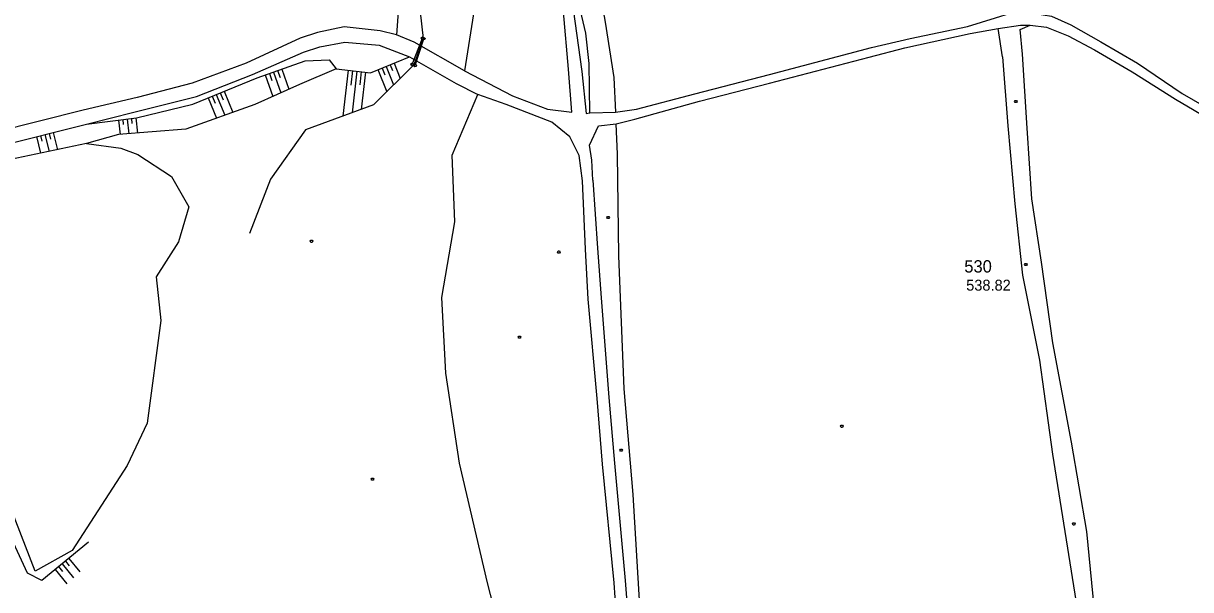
# Model space of a CAD drawing. Extents: x -664960 to -662754, y -993849 to -991145.
# Drawn here: x -663773.7 to -663452.1, y -992215.3 to -992059.4 of the extents above; entities that cross this region are included whole.
import ezdxf

# ---------------------------------------------------------------- set-up
doc = ezdxf.new("R2010")
doc.units = 0
for name, color, linetype in [('Vrstva 1', 7, 'Continuous'), ('Vrstva 13', 7, 'Continuous'), ('Vrstva 24', 7, 'Continuous'), ('Vrstva 27', 7, 'Continuous'), ('Vrstva 28', 7, 'Continuous'), ('Vrstva 33', 7, 'Continuous'), ('Vrstva 63', 7, 'Continuous'), ('Vrstva 8', 7, 'Continuous')]:
    doc.layers.add(name, color=color, linetype=linetype)

msp = doc.modelspace()

# ---------------------------------------------------------------- linework, layer by layer
at = {"layer": 'Vrstva 13'}
for points in [[(-663500.081, -992080.583), (-663499.901, -992080.883), (-663500.081, -992081.183), (-663500.441, -992081.183), (-663500.621, -992080.883), (-663500.441, -992080.583), (-663500.081, -992080.583)], [(-663612.408, -992112.523), (-663612.228, -992112.823), (-663612.408, -992113.123), (-663612.768, -992113.123), (-663612.948, -992112.823), (-663612.768, -992112.523), (-663612.408, -992112.523)], [(-663694.093, -992119.079), (-663693.913, -992119.379), (-663694.093, -992119.679), (-663694.453, -992119.679), (-663694.633, -992119.379), (-663694.453, -992119.079), (-663694.093, -992119.079)], [(-663636.781, -992145.489), (-663636.601, -992145.789), (-663636.781, -992146.089), (-663637.141, -992146.089), (-663637.321, -992145.789), (-663637.141, -992145.489), (-663636.781, -992145.489)], [(-663548.037, -992170.022), (-663547.857, -992170.322), (-663548.037, -992170.622), (-663548.397, -992170.622), (-663548.577, -992170.322), (-663548.397, -992170.022), (-663548.037, -992170.022)], [(-663608.823, -992176.582), (-663608.643, -992176.882), (-663608.823, -992177.182), (-663609.183, -992177.182), (-663609.363, -992176.882), (-663609.183, -992176.582), (-663608.823, -992176.582)], [(-663677.291, -992184.592), (-663677.111, -992184.892), (-663677.291, -992185.192), (-663677.651, -992185.192), (-663677.831, -992184.892), (-663677.651, -992184.592), (-663677.291, -992184.592)], [(-663484.097, -992196.909), (-663483.917, -992197.209), (-663484.097, -992197.509), (-663484.457, -992197.509), (-663484.637, -992197.209), (-663484.457, -992196.909), (-663484.097, -992196.909)]]:
    msp.add_lwpolyline(points, dxfattribs=at)
at = {"layer": 'Vrstva 24'}
for p, q in [((-663666.555, -992070.68), (-663663.701, -992063.457)), ((-663665.708, -992070.984), (-663663.325, -992063.591))]:
    msp.add_line(p, q, dxfattribs=at)
for points in [[(-663663.979, -992063.669), (-663664.036, -992063.324), (-663663.759, -992063.111), (-663663.424, -992063.244), (-663663.367, -992063.589), (-663663.644, -992063.802), (-663663.979, -992063.669)], [(-663663.555, -992063.328), (-663663.214, -992063.249), (-663662.984, -992063.512), (-663663.095, -992063.855), (-663663.436, -992063.934), (-663663.666, -992063.67), (-663663.555, -992063.328)], [(-663666.278, -992070.467), (-663666.221, -992070.812), (-663666.498, -992071.025), (-663666.833, -992070.893), (-663666.89, -992070.548), (-663666.613, -992070.335), (-663666.278, -992070.467)], [(-663665.938, -992070.72), (-663665.597, -992070.641), (-663665.367, -992070.905), (-663665.478, -992071.247), (-663665.819, -992071.326), (-663666.049, -992071.063), (-663665.938, -992070.72)]]:
    msp.add_lwpolyline(points, dxfattribs=at)
at = {"layer": 'Vrstva 27'}
for p, q in [((-663617.662, -992084.005), (-663610.509, -992083.791)), ((-663610.371, -992087.031), (-663610.371, -992087.031)), ((-663619.645, -992102.742), (-663620.564, -992095.802))]:
    msp.add_line(p, q, dxfattribs=at)
for points in [[(-663652.149, -992072.457), (-663638.894, -992079.322), (-663629.252, -992082.973), (-663622.572, -992083.804), (-663623.507, -992071.963), (-663624.89, -992056.198), (-663630.063, -992031.166), (-663634.545, -992007.215), (-663637.859, -991989.522), (-663641.354, -991966.119), (-663644.017, -991941.494), (-663646.236, -991915.956), (-663649.418, -991889.892), (-663652.546, -991864.285), (-663654.41, -991840.241), (-663656.328, -991820.074), (-663658.665, -991801.934), (-663661.329, -991790.355), (-663663.806, -991781.544)], [(-663660.976, -991780.777), (-663658.558, -991789.771), (-663655.323, -991801.705), (-663653.202, -991819.768), (-663651.587, -991840.172), (-663649.787, -991863.83), (-663646.312, -991889.394), (-663643.411, -991916.091), (-663641.041, -991940.893), (-663638.598, -991965.955), (-663635.066, -991988.904), (-663631.676, -992006.332), (-663627.229, -992030.816), (-663622.18, -992055.438), (-663619.865, -992072.617), (-663618.624, -992084.162), (-663617.662, -992084.005)], [(-663610.509, -992083.791), (-663604.798, -992083.037), (-663588.741, -992078.775), (-663568.158, -992073.414), (-663540.034, -992066.054), (-663529.382, -992063.582), (-663513.636, -992060.192), (-663505.874, -992057.816)], [(-663505.874, -992057.816), (-663501.741, -992056.574), (-663497.34, -992056.267), (-663490.468, -992057.436), (-663485.138, -992059.768), (-663476.877, -992064.439), (-663466.765, -992070.371), (-663454.437, -992078.707), (-663436.313, -992089.167), (-663416.04, -992100.061), (-663402.598, -992105.966), (-663390.777, -992109.645), (-663381.893, -992111.637), (-663376.011, -992112.573), (-663374.014, -992111.876)], [(-663652.149, -992072.457), (-663666.048, -992064.522), (-663670.915, -992062.515), (-663675.397, -992061.433), (-663685.315, -992060.33), (-663692.602, -992061.892), (-663697.435, -992063.44), (-663712.242, -992070.367), (-663727.163, -992075.883), (-663742.301, -992079.812), (-663757.17, -992083.235), (-663781.317, -992089.372), (-663789.254, -992091.031), (-663815.063, -992094.6), (-663832.035, -992101.429), (-663841.787, -992109.827), (-663853.332, -992124.858), (-663861.753, -992138.392), (-663865.565, -992146.055), (-663870.358, -992158.296), (-663873.442, -992172.032), (-663874.279, -992185.452), (-663873.423, -992201.852), (-663871.565, -992214.969)], [(-663610.371, -992087.031), (-663605.274, -992085.712), (-663587.403, -992080.826), (-663568.125, -992075.859), (-663540.707, -992068.649), (-663530.863, -992066.12), (-663512.89, -992062.21), (-663505.164, -992060.778)], [(-663505.164, -992060.778), (-663499.035, -992059.84), (-663496.315, -992059.878), (-663491.826, -992060.396), (-663485.827, -992062.825), (-663478.629, -992066.63), (-663468.226, -992072.7), (-663456.349, -992080.226), (-663437.31, -992091.482), (-663416.912, -992102.28), (-663405.126, -992108.137), (-663391.371, -992112.531), (-663381.874, -992114.453), (-663376.408, -992115.427), (-663372.877, -992116.89), (-663369.899, -992119.472)], [(-663867.768, -992214.752), (-663869.372, -992201.64), (-663870.276, -992185.241), (-663869.416, -992173.115), (-663866.625, -992159.618), (-663862.399, -992148.688), (-663858.277, -992140.51), (-663850.111, -992126.922), (-663839.032, -992112.926), (-663829.283, -992104.516), (-663813.981, -992098.887), (-663790.431, -992094.971), (-663780.543, -992093.142), (-663756.27, -992087.113), (-663743.198, -992083.857), (-663725.949, -992079.492), (-663710.496, -992073.411), (-663696.524, -992067.259), (-663692.016, -992065.833), (-663685.143, -992064.515), (-663675.656, -992065.396), (-663667.253, -992068.6), (-663654.396, -992075.969), (-663648.46, -992078.95)], [(-663628.118, -992086.576), (-663640.641, -992081.732), (-663648.46, -992078.95)], [(-663620.564, -992095.802), (-663623.092, -992090.585), (-663628.118, -992086.576)], [(-663617.68, -992092.91), (-663615.26, -992087.61), (-663610.371, -992087.031)], [(-663616.772, -992102.525), (-663617.1, -992097.01), (-663617.68, -992092.91)], [(-663609.18, -992284), (-663609.46, -992267.9), (-663609.2, -992261.28), (-663609.26, -992237.69), (-663610.89, -992213.38), (-663614.18, -992180.71), (-663615.56, -992162.64), (-663618.05, -992135.28), (-663618.78, -992121.53), (-663619.645, -992102.742)], [(-663616.772, -992102.525), (-663615.49, -992121.31), (-663614.49, -992134.95), (-663612.38, -992162.38), (-663610.82, -992180.49), (-663607.92, -992212.78), (-663606.07, -992236.58), (-663606.22, -992261.4), (-663605.35, -992288.4)]]:
    msp.add_lwpolyline(points, dxfattribs=at)
at = {"layer": 'Vrstva 28'}
for p, q in [((-663667.952, -992025.484), (-663663.513, -992063.524)), ((-663663.513, -992063.524), (-663666.132, -992070.832))]:
    msp.add_line(p, q, dxfattribs=at)
msp.add_lwpolyline([(-663666.132, -992070.832), (-663677.21, -992081.835), (-663695.934, -992088.709), (-663705.595, -992102.302), (-663711.407, -992117.193)], dxfattribs=at)
at = {"layer": 'Vrstva 33'}
msp.add_lwpolyline([(-663625.96, -992122.04), (-663625.78, -992122.34), (-663625.96, -992122.64), (-663626.32, -992122.64), (-663626.5, -992122.34), (-663626.32, -992122.04), (-663625.96, -992122.04)], dxfattribs=at)
at = {"layer": 'Vrstva 63'}
for p, q in [((-663503.985, -992068.553), (-663505.164, -992060.778)), ((-663702.494, -992071.967), (-663700.511, -992077.529)), ((-663684.167, -992072.26), (-663685.623, -992084.923)), ((-663675.975, -992072.114), (-663673.531, -992078.181)), ((-663674.862, -992071.665), (-663674.111, -992073.529)), ((-663673.749, -992071.217), (-663671.683, -992076.345)), ((-663672.636, -992070.769), (-663672.011, -992072.32)), ((-663671.523, -992070.32), (-663669.835, -992074.51)), ((-663707.015, -992073.579), (-663704.904, -992079.502)), ((-663705.885, -992073.176), (-663705.192, -992075.118)), ((-663704.754, -992072.773), (-663702.708, -992078.515)), ((-663703.624, -992072.37), (-663702.953, -992074.252)), ((-663682.975, -992072.397), (-663683.437, -992076.414)), ((-663681.783, -992072.534), (-663683.101, -992083.997)), ((-663680.591, -992072.671), (-663681.007, -992076.289)), ((-663679.399, -992072.808), (-663680.579, -992083.071)), ((-663719.416, -992078.542), (-663718.632, -992080.456)), ((-663718.306, -992078.087), (-663715.928, -992083.888)), ((-663722.747, -992079.907), (-663720.455, -992085.5)), ((-663721.637, -992079.452), (-663720.867, -992081.332)), ((-663720.527, -992078.997), (-663718.192, -992084.694)), ((-663747.481, -992086.012), (-663746.986, -992089.968)), ((-663746.29, -992085.863), (-663746.123, -992087.198)), ((-663745.1, -992085.714), (-663744.591, -992089.776)), ((-663743.909, -992085.565), (-663743.738, -992086.935)), ((-663742.718, -992085.416), (-663742.197, -992089.583)), ((-663609.968, -992095.397), (-663610.371, -992087.031)), ((-663770.069, -992090.54), (-663768.927, -992095.137)), ((-663768.904, -992090.251), (-663768.52, -992091.796)), ((-663767.739, -992089.961), (-663766.576, -992094.646)), ((-663766.575, -992089.672), (-663766.184, -992091.247)), ((-663765.41, -992089.383), (-663764.225, -992094.154)), ((-663761.146, -992206.687), (-663758.117, -992210.394)), ((-663764.863, -992209.724), (-663761.642, -992213.665)), ((-663763.934, -992208.965), (-663762.877, -992210.258)), ((-663763.005, -992208.206), (-663759.879, -992212.03)), ((-663762.075, -992207.446), (-663761.051, -992208.7))]:
    msp.add_line(p, q, dxfattribs=at)
for points in [[(-663617.662, -992084.005), (-663617.796, -992070.405), (-663618.685, -992062.035), (-663620.6, -992054.289), (-663624.555, -992034.438), (-663627.573, -992021.077), (-663630.439, -992005.417), (-663633.594, -991988.6), (-663636.017, -991965.823), (-663639.158, -991940.551), (-663641.433, -991916.279), (-663644.548, -991888.909), (-663648.221, -991863.623), (-663649.938, -991840.103), (-663650.821, -991819.63), (-663650.995, -991810.793), (-663652.021, -991800.876), (-663653.776, -991788.518), (-663656.114, -991774.485), (-663657.935, -991762.249), (-663658.157, -991746.16), (-663659.154, -991720.205)], [(-663625.612, -991996.822), (-663623.58, -992006.69), (-663618.949, -992028.863), (-663616.597, -992040.728), (-663613.419, -992059.024), (-663611.042, -992074.3), (-663610.509, -992083.791)], [(-663687.235, -992025.666), (-663672.631, -992026.425), (-663669.875, -992048.621), (-663670.915, -992062.515)], [(-663649.704, -992056.772), (-663652.149, -992072.457)], [(-663498.448, -992067.861), (-663499.131, -992061.103), (-663496.315, -992059.878)], [(-663756.27, -992087.113), (-663742.496, -992085.388), (-663726.974, -992081.64), (-663709.26, -992074.379), (-663696.074, -992069.679), (-663689.436, -992069.427), (-663687.539, -992071.872), (-663678.076, -992072.96), (-663667.253, -992068.6)], [(-663503.985, -992068.553), (-663502.49, -992087.58), (-663500.52, -992109.05), (-663498.42, -992128.71), (-663493.79, -992152.11), (-663490.17, -992178.03), (-663483.06, -992222.86), (-663480.63, -992245.25), (-663480.32, -992267.2)], [(-663475.97, -992273.64), (-663476, -992255.14), (-663478.3, -992223.8), (-663480.74, -992199.31), (-663484.94, -992174.65), (-663490.09, -992147.35), (-663493.26, -992125.09), (-663495.9, -992107.68), (-663497.17, -992088.23), (-663498.448, -992067.861)], [(-663687.539, -992071.872), (-663697.594, -992076.22), (-663709.856, -992081.725), (-663728.917, -992088.514), (-663747.464, -992090.007), (-663756.253, -992092.487), (-663780.731, -992097.606), (-663792.314, -992099.303), (-663814.145, -992102.581), (-663827.055, -992107.734), (-663836.598, -992115.531), (-663846.58, -992127.329), (-663856.223, -992141.469), (-663859.063, -992150.47), (-663866.625, -992159.618)], [(-663633.3, -992287.85), (-663635.84, -992266.79), (-663638.48, -992251.41), (-663641.84, -992228.79), (-663645.82, -992213.4), (-663653.56, -992180.51), (-663657.32, -992155.71), (-663658.36, -992134.88), (-663654.79, -992114.04), (-663655.56, -992095.7), (-663648.46, -992078.95)], [(-663756.253, -992092.487), (-663746.828, -992093.758), (-663742.121, -992095.479), (-663732.85, -992101.523), (-663728.116, -992109.932), (-663730.943, -992119.569), (-663737.051, -992129.159), (-663735.83, -992141.172), (-663739.547, -992169.479), (-663745.097, -992181.09), (-663760.244, -992204.525), (-663770.418, -992210.225), (-663778.389, -992189.549), (-663784.771, -992179.426), (-663793.726, -992169.45), (-663808.984, -992173.8), (-663812.912, -992183.474)], [(-663481.51, -992286.47), (-663501.02, -992286.13), (-663518.86, -992285.48), (-663556.12, -992281.38), (-663564.44, -992280.33), (-663573.46, -992278.84), (-663585.77, -992276.23), (-663602.73, -992270.11), (-663602.69, -992238.93), (-663603.85, -992219.76), (-663605.7, -992189.06), (-663608.17, -992160.04), (-663609.68, -992123.43), (-663609.968, -992095.397)], [(-663755.675, -992202.216), (-663768.567, -992212.751), (-663772.484, -992210.734), (-663781.84, -992190.688), (-663786.31, -992183.558), (-663794.872, -992173.974), (-663804.64, -992174.043), (-663812.912, -992183.474)]]:
    msp.add_lwpolyline(points, dxfattribs=at)
at = {"layer": 'Vrstva 8'}
msp.add_lwpolyline([(-663497.38, -992125.47), (-663497.2, -992125.77), (-663497.38, -992126.07), (-663497.74, -992126.07), (-663497.92, -992125.77), (-663497.74, -992125.47), (-663497.38, -992125.47)], dxfattribs=at)

# ---------------------------------------------------------------- texts
at = {"layer": 'Vrstva 1'}
msp.add_text('530', height=3.4, dxfattribs=at).set_placement((-663514.481, -992127.984))
at = {"layer": 'Vrstva 63'}
msp.add_text('538.82', height=3, dxfattribs=at).set_placement((-663513.957, -992132.964))

doc.saveas('drawing.dxf')
